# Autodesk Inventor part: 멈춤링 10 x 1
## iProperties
IsCustomPart: 0
Company: 한국ATC센터
Created: 2009-02
Part Number: 멈춤링 10 x 1
Material: Steel, Mild
Description: 리테이닝 링(C형)
Document SubType Name: Modeling
Standard: KS B 1336
Designer: KYOUNG IL JANG
Standards Organization: KS
Language: ko-KR
Size Designation: 10 x 1
Categories: <MemberInstance><Categories><Category DisplayName="샤프트 부품" InternalName="7f7aeb1f-a693-4053-b835-cee3144e0d98" Mnemonic="SHFT"><Category DisplayName="써클립" Inter
Density: 7.86 g/cm^3
Mass: 0.423084 g
Surface Area: 1.9243 cm^2
Volume: 0.0538275 cm^3
Author: KYOUNG IL JANG
